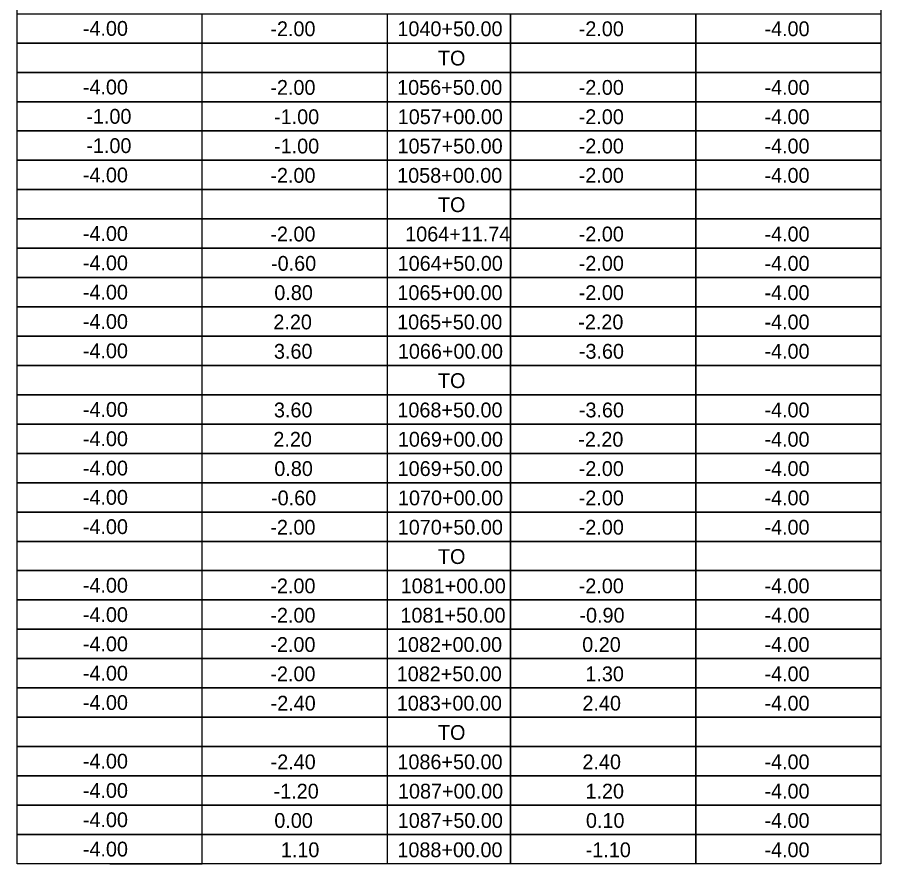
# Model space of a CAD drawing. Extents: x 1026502 to 1027102, y 781811 to 782040.
# Drawn here: x 1027034.42 to 1027062.42, y 781866.07 to 781893.52 of the extents above; entities that cross this region are included whole.
import ezdxf

# ---------------------------------------------------------------- set-up
doc = ezdxf.new("R2010")
doc.units = 0
for name, color, linetype in [('ANNOTATION', 7, 'Continuous'), ('BORDER', 7, 'Continuous'), ('DIMENSIONS', 7, 'Continuous')]:
    doc.layers.add(name, color=color, linetype=linetype)

msp = doc.modelspace()

# ---------------------------------------------------------------- linework, layer by layer
at = {"layer": 'ANNOTATION'}
msp.add_lwpolyline([(1027034.415, 781920.244), (1027062.415, 781920.244), (1027062.415, 781866.071), (1027034.415, 781866.071)], close=True, dxfattribs=at)
at = {"layer": 'BORDER'}
for p, q in [((1027037.415, 781892.682), (1027034.415, 781892.682)), ((1027037.415, 781892.682), (1027034.415, 781892.682)), ((1027037.415, 781892.682), (1027040.415, 781892.682)), ((1027037.415, 781891.732), (1027034.415, 781891.732)), ((1027037.415, 781891.732), (1027034.415, 781891.732)), ((1027037.415, 781891.732), (1027040.415, 781891.732)), ((1027037.415, 781890.781), (1027034.415, 781890.781)), ((1027037.415, 781890.781), (1027034.415, 781890.781)), ((1027037.415, 781890.781), (1027040.415, 781890.781)), ((1027037.415, 781889.831), (1027034.415, 781889.831)), ((1027037.415, 781889.831), (1027034.415, 781889.831)), ((1027037.415, 781889.831), (1027040.415, 781889.831)), ((1027037.415, 781888.881), (1027034.415, 781888.881)), ((1027037.415, 781888.881), (1027034.415, 781888.881)), ((1027037.415, 781888.881), (1027040.415, 781888.881)), ((1027037.415, 781887.93), (1027034.415, 781887.93)), ((1027037.415, 781887.93), (1027034.415, 781887.93)), ((1027037.415, 781887.93), (1027040.415, 781887.93)), ((1027037.415, 781886.98), (1027034.415, 781886.98)), ((1027037.415, 781886.98), (1027034.415, 781886.98)), ((1027037.415, 781886.98), (1027040.415, 781886.98)), ((1027037.415, 781886.029), (1027034.415, 781886.029)), ((1027037.415, 781886.029), (1027034.415, 781886.029)), ((1027037.415, 781886.029), (1027040.415, 781886.029)), ((1027037.415, 781885.079), (1027034.415, 781885.079)), ((1027037.415, 781885.079), (1027034.415, 781885.079)), ((1027037.415, 781885.079), (1027040.415, 781885.079)), ((1027037.415, 781884.129), (1027034.415, 781884.129)), ((1027037.415, 781884.129), (1027034.415, 781884.129)), ((1027037.415, 781884.129), (1027040.415, 781884.129)), ((1027037.415, 781883.178), (1027034.415, 781883.178)), ((1027037.415, 781883.178), (1027034.415, 781883.178)), ((1027037.415, 781883.178), (1027040.415, 781883.178)), ((1027037.415, 781882.228), (1027034.415, 781882.228)), ((1027037.415, 781882.228), (1027034.415, 781882.228)), ((1027037.415, 781882.228), (1027040.415, 781882.228)), ((1027037.415, 781881.277), (1027034.415, 781881.277)), ((1027037.415, 781881.277), (1027034.415, 781881.277)), ((1027037.415, 781881.277), (1027040.415, 781881.277)), ((1027037.415, 781880.327), (1027034.415, 781880.327)), ((1027037.415, 781880.327), (1027034.415, 781880.327)), ((1027037.415, 781880.327), (1027040.415, 781880.327)), ((1027037.415, 781879.377), (1027034.415, 781879.377)), ((1027037.415, 781879.377), (1027034.415, 781879.377)), ((1027037.415, 781879.377), (1027040.415, 781879.377)), ((1027037.415, 781878.426), (1027034.415, 781878.426)), ((1027037.415, 781878.426), (1027034.415, 781878.426)), ((1027037.415, 781878.426), (1027040.415, 781878.426)), ((1027037.415, 781877.476), (1027034.415, 781877.476)), ((1027037.415, 781877.476), (1027034.415, 781877.476)), ((1027037.415, 781877.476), (1027040.415, 781877.476)), ((1027037.415, 781876.525), (1027034.415, 781876.525)), ((1027037.415, 781876.525), (1027034.415, 781876.525)), ((1027037.415, 781876.525), (1027040.415, 781876.525)), ((1027037.415, 781875.575), (1027034.415, 781875.575)), ((1027037.415, 781875.575), (1027034.415, 781875.575)), ((1027037.415, 781875.575), (1027040.415, 781875.575)), ((1027037.415, 781874.625), (1027034.415, 781874.625)), ((1027037.415, 781874.625), (1027034.415, 781874.625)), ((1027037.415, 781874.625), (1027040.415, 781874.625)), ((1027037.415, 781873.674), (1027034.415, 781873.674)), ((1027037.415, 781873.674), (1027034.415, 781873.674)), ((1027037.415, 781873.674), (1027040.415, 781873.674)), ((1027037.415, 781872.724), (1027034.415, 781872.724)), ((1027037.415, 781872.724), (1027034.415, 781872.724)), ((1027037.415, 781872.724), (1027040.415, 781872.724)), ((1027037.415, 781871.773), (1027034.415, 781871.773)), ((1027037.415, 781871.773), (1027034.415, 781871.773)), ((1027037.415, 781871.773), (1027040.415, 781871.773)), ((1027037.415, 781870.823), (1027034.415, 781870.823)), ((1027037.415, 781870.823), (1027034.415, 781870.823)), ((1027037.415, 781870.823), (1027040.415, 781870.823)), ((1027037.415, 781869.873), (1027034.415, 781869.873)), ((1027037.415, 781869.873), (1027034.415, 781869.873)), ((1027037.415, 781869.873), (1027040.415, 781869.873)), ((1027037.415, 781868.922), (1027034.415, 781868.922)), ((1027037.415, 781868.922), (1027034.415, 781868.922)), ((1027037.415, 781868.922), (1027040.415, 781868.922)), ((1027037.415, 781867.972), (1027034.415, 781867.972)), ((1027037.415, 781867.972), (1027034.415, 781867.972)), ((1027037.415, 781867.972), (1027040.415, 781867.972)), ((1027037.415, 781867.021), (1027034.415, 781867.021)), ((1027037.415, 781867.021), (1027034.415, 781867.021)), ((1027037.415, 781867.021), (1027040.415, 781867.021)), ((1027037.415, 781866.071), (1027034.415, 781866.071)), ((1027037.415, 781866.071), (1027034.415, 781866.071)), ((1027037.415, 781866.071), (1027040.415, 781866.071))]:
    msp.add_line(p, q, dxfattribs=at)
for points in [[(1027034.415, 781893.633), (1027062.415, 781893.633), (1027062.415, 781892.682), (1027034.415, 781892.682)], [(1027034.415, 781892.682), (1027062.415, 781892.682), (1027062.415, 781891.732), (1027034.415, 781891.732)], [(1027034.415, 781891.732), (1027062.415, 781891.732), (1027062.415, 781890.781), (1027034.415, 781890.781)], [(1027034.415, 781890.781), (1027062.415, 781890.781), (1027062.415, 781889.831), (1027034.415, 781889.831)], [(1027034.415, 781889.831), (1027062.415, 781889.831), (1027062.415, 781888.881), (1027034.415, 781888.881)], [(1027034.415, 781888.881), (1027062.415, 781888.881), (1027062.415, 781887.93), (1027034.415, 781887.93)], [(1027034.415, 781887.93), (1027062.415, 781887.93), (1027062.415, 781886.98), (1027034.415, 781886.98)], [(1027034.415, 781886.98), (1027062.415, 781886.98), (1027062.415, 781886.029), (1027034.415, 781886.029)], [(1027034.415, 781886.029), (1027062.415, 781886.029), (1027062.415, 781885.079), (1027034.415, 781885.079)], [(1027034.415, 781885.079), (1027062.415, 781885.079), (1027062.415, 781884.129), (1027034.415, 781884.129)], [(1027034.415, 781884.129), (1027062.415, 781884.129), (1027062.415, 781883.178), (1027034.415, 781883.178)], [(1027034.415, 781883.178), (1027062.415, 781883.178), (1027062.415, 781882.228), (1027034.415, 781882.228)], [(1027034.415, 781882.228), (1027062.415, 781882.228), (1027062.415, 781881.277), (1027034.415, 781881.277)], [(1027034.415, 781881.277), (1027062.415, 781881.277), (1027062.415, 781880.327), (1027034.415, 781880.327)], [(1027034.415, 781880.327), (1027062.415, 781880.327), (1027062.415, 781879.377), (1027034.415, 781879.377)], [(1027034.415, 781879.377), (1027062.415, 781879.377), (1027062.415, 781878.426), (1027034.415, 781878.426)], [(1027034.415, 781878.426), (1027062.415, 781878.426), (1027062.415, 781877.476), (1027034.415, 781877.476)], [(1027034.415, 781877.476), (1027062.415, 781877.476), (1027062.415, 781876.525), (1027034.415, 781876.525)], [(1027034.415, 781876.525), (1027062.415, 781876.525), (1027062.415, 781875.575), (1027034.415, 781875.575)], [(1027034.415, 781875.575), (1027062.415, 781875.575), (1027062.415, 781874.625), (1027034.415, 781874.625)], [(1027034.415, 781874.625), (1027062.415, 781874.625), (1027062.415, 781873.674), (1027034.415, 781873.674)], [(1027034.415, 781873.674), (1027062.415, 781873.674), (1027062.415, 781872.724), (1027034.415, 781872.724)], [(1027034.415, 781872.724), (1027062.415, 781872.724), (1027062.415, 781871.773), (1027034.415, 781871.773)], [(1027034.415, 781871.773), (1027062.415, 781871.773), (1027062.415, 781870.823), (1027034.415, 781870.823)], [(1027034.415, 781870.823), (1027062.415, 781870.823), (1027062.415, 781869.873), (1027034.415, 781869.873)], [(1027034.415, 781869.873), (1027062.415, 781869.873), (1027062.415, 781868.922), (1027034.415, 781868.922)], [(1027034.415, 781868.922), (1027062.415, 781868.922), (1027062.415, 781867.972), (1027034.415, 781867.972)], [(1027034.415, 781867.972), (1027062.415, 781867.972), (1027062.415, 781867.021), (1027034.415, 781867.021)], [(1027034.415, 781867.021), (1027062.415, 781867.021), (1027062.415, 781866.071), (1027034.415, 781866.071)]]:
    msp.add_lwpolyline(points, close=True, dxfattribs=at)
for points in [[(1027046.415, 781893.633), (1027046.415, 781892.682), (1027040.415, 781892.682), (1027040.415, 781893.633)], [(1027050.415, 781893.633), (1027050.415, 781892.682), (1027046.415, 781892.682)], [(1027056.415, 781893.633), (1027056.415, 781892.682), (1027050.415, 781892.682), (1027050.415, 781893.633)], [(1027062.415, 781893.633), (1027062.415, 781892.682), (1027056.415, 781892.682), (1027056.415, 781893.633)], [(1027046.415, 781892.682), (1027046.415, 781891.732), (1027040.415, 781891.732), (1027040.415, 781892.682)], [(1027050.415, 781892.682), (1027050.415, 781891.732), (1027046.415, 781891.732)], [(1027056.415, 781892.682), (1027056.415, 781891.732), (1027050.415, 781891.732), (1027050.415, 781892.682)], [(1027062.415, 781892.682), (1027062.415, 781891.732), (1027056.415, 781891.732), (1027056.415, 781892.682)], [(1027046.415, 781891.732), (1027046.415, 781890.781), (1027040.415, 781890.781), (1027040.415, 781891.732)], [(1027050.415, 781891.732), (1027050.415, 781890.781), (1027046.415, 781890.781)], [(1027056.415, 781891.732), (1027056.415, 781890.781), (1027050.415, 781890.781), (1027050.415, 781891.732)], [(1027062.415, 781891.732), (1027062.415, 781890.781), (1027056.415, 781890.781), (1027056.415, 781891.732)], [(1027046.415, 781890.781), (1027046.415, 781889.831), (1027040.415, 781889.831), (1027040.415, 781890.781)], [(1027050.415, 781890.781), (1027050.415, 781889.831), (1027046.415, 781889.831)], [(1027056.415, 781890.781), (1027056.415, 781889.831), (1027050.415, 781889.831), (1027050.415, 781890.781)], [(1027062.415, 781890.781), (1027062.415, 781889.831), (1027056.415, 781889.831), (1027056.415, 781890.781)], [(1027046.415, 781889.831), (1027046.415, 781888.881), (1027040.415, 781888.881), (1027040.415, 781889.831)], [(1027050.415, 781889.831), (1027050.415, 781888.881), (1027046.415, 781888.881)], [(1027056.415, 781889.831), (1027056.415, 781888.881), (1027050.415, 781888.881), (1027050.415, 781889.831)], [(1027062.415, 781889.831), (1027062.415, 781888.881), (1027056.415, 781888.881), (1027056.415, 781889.831)], [(1027046.415, 781888.881), (1027046.415, 781887.93), (1027040.415, 781887.93), (1027040.415, 781888.881)], [(1027050.415, 781888.881), (1027050.415, 781887.93), (1027046.415, 781887.93)], [(1027056.415, 781888.881), (1027056.415, 781887.93), (1027050.415, 781887.93), (1027050.415, 781888.881)], [(1027062.415, 781888.881), (1027062.415, 781887.93), (1027056.415, 781887.93), (1027056.415, 781888.881)], [(1027046.415, 781887.93), (1027046.415, 781886.98), (1027040.415, 781886.98), (1027040.415, 781887.93)], [(1027050.415, 781887.93), (1027050.415, 781886.98), (1027046.415, 781886.98)], [(1027056.415, 781887.93), (1027056.415, 781886.98), (1027050.415, 781886.98), (1027050.415, 781887.93)], [(1027062.415, 781887.93), (1027062.415, 781886.98), (1027056.415, 781886.98), (1027056.415, 781887.93)], [(1027046.415, 781886.98), (1027046.415, 781886.029), (1027040.415, 781886.029), (1027040.415, 781886.98)], [(1027050.415, 781886.98), (1027050.415, 781886.029), (1027046.415, 781886.029)], [(1027056.415, 781886.98), (1027056.415, 781886.029), (1027050.415, 781886.029), (1027050.415, 781886.98)], [(1027062.415, 781886.98), (1027062.415, 781886.029), (1027056.415, 781886.029), (1027056.415, 781886.98)], [(1027046.415, 781886.029), (1027046.415, 781885.079), (1027040.415, 781885.079), (1027040.415, 781886.029)], [(1027050.415, 781886.029), (1027050.415, 781885.079), (1027046.415, 781885.079)], [(1027056.415, 781886.029), (1027056.415, 781885.079), (1027050.415, 781885.079), (1027050.415, 781886.029)], [(1027062.415, 781886.029), (1027062.415, 781885.079), (1027056.415, 781885.079), (1027056.415, 781886.029)], [(1027046.415, 781885.079), (1027046.415, 781884.129), (1027040.415, 781884.129), (1027040.415, 781885.079)], [(1027050.415, 781885.079), (1027050.415, 781884.129), (1027046.415, 781884.129)], [(1027056.415, 781885.079), (1027056.415, 781884.129), (1027050.415, 781884.129), (1027050.415, 781885.079)], [(1027062.415, 781885.079), (1027062.415, 781884.129), (1027056.415, 781884.129), (1027056.415, 781885.079)], [(1027046.415, 781884.129), (1027046.415, 781883.178), (1027040.415, 781883.178), (1027040.415, 781884.129)], [(1027050.415, 781884.129), (1027050.415, 781883.178), (1027046.415, 781883.178)], [(1027056.415, 781884.129), (1027056.415, 781883.178), (1027050.415, 781883.178), (1027050.415, 781884.129)], [(1027062.415, 781884.129), (1027062.415, 781883.178), (1027056.415, 781883.178), (1027056.415, 781884.129)], [(1027046.415, 781883.178), (1027046.415, 781882.228), (1027040.415, 781882.228), (1027040.415, 781883.178)], [(1027050.415, 781883.178), (1027050.415, 781882.228), (1027046.415, 781882.228)], [(1027056.415, 781883.178), (1027056.415, 781882.228), (1027050.415, 781882.228), (1027050.415, 781883.178)], [(1027062.415, 781883.178), (1027062.415, 781882.228), (1027056.415, 781882.228), (1027056.415, 781883.178)], [(1027046.415, 781882.228), (1027046.415, 781881.277), (1027040.415, 781881.277), (1027040.415, 781882.228)], [(1027050.415, 781882.228), (1027050.415, 781881.277), (1027046.415, 781881.277)], [(1027056.415, 781882.228), (1027056.415, 781881.277), (1027050.415, 781881.277), (1027050.415, 781882.228)], [(1027062.415, 781882.228), (1027062.415, 781881.277), (1027056.415, 781881.277), (1027056.415, 781882.228)], [(1027046.415, 781881.277), (1027046.415, 781880.327), (1027040.415, 781880.327), (1027040.415, 781881.277)], [(1027050.415, 781881.277), (1027050.415, 781880.327), (1027046.415, 781880.327)], [(1027056.415, 781881.277), (1027056.415, 781880.327), (1027050.415, 781880.327), (1027050.415, 781881.277)], [(1027062.415, 781881.277), (1027062.415, 781880.327), (1027056.415, 781880.327), (1027056.415, 781881.277)], [(1027046.415, 781880.327), (1027046.415, 781879.377), (1027040.415, 781879.377), (1027040.415, 781880.327)], [(1027050.415, 781880.327), (1027050.415, 781879.377), (1027046.415, 781879.377)], [(1027056.415, 781880.327), (1027056.415, 781879.377), (1027050.415, 781879.377), (1027050.415, 781880.327)], [(1027062.415, 781880.327), (1027062.415, 781879.377), (1027056.415, 781879.377), (1027056.415, 781880.327)], [(1027046.415, 781879.377), (1027046.415, 781878.426), (1027040.415, 781878.426), (1027040.415, 781879.377)], [(1027050.415, 781879.377), (1027050.415, 781878.426), (1027046.415, 781878.426)], [(1027056.415, 781879.377), (1027056.415, 781878.426), (1027050.415, 781878.426), (1027050.415, 781879.377)], [(1027062.415, 781879.377), (1027062.415, 781878.426), (1027056.415, 781878.426), (1027056.415, 781879.377)], [(1027046.415, 781878.426), (1027046.415, 781877.476), (1027040.415, 781877.476), (1027040.415, 781878.426)], [(1027050.415, 781878.426), (1027050.415, 781877.476), (1027046.415, 781877.476)], [(1027056.415, 781878.426), (1027056.415, 781877.476), (1027050.415, 781877.476), (1027050.415, 781878.426)], [(1027062.415, 781878.426), (1027062.415, 781877.476), (1027056.415, 781877.476), (1027056.415, 781878.426)], [(1027046.415, 781877.476), (1027046.415, 781876.525), (1027040.415, 781876.525), (1027040.415, 781877.476)], [(1027050.415, 781877.476), (1027050.415, 781876.525), (1027046.415, 781876.525)], [(1027056.415, 781877.476), (1027056.415, 781876.525), (1027050.415, 781876.525), (1027050.415, 781877.476)], [(1027062.415, 781877.476), (1027062.415, 781876.525), (1027056.415, 781876.525), (1027056.415, 781877.476)], [(1027046.415, 781876.525), (1027046.415, 781875.575), (1027040.415, 781875.575), (1027040.415, 781876.525)], [(1027050.415, 781876.525), (1027050.415, 781875.575), (1027046.415, 781875.575)], [(1027056.415, 781876.525), (1027056.415, 781875.575), (1027050.415, 781875.575), (1027050.415, 781876.525)], [(1027062.415, 781876.525), (1027062.415, 781875.575), (1027056.415, 781875.575), (1027056.415, 781876.525)], [(1027046.415, 781875.575), (1027046.415, 781874.625), (1027040.415, 781874.625), (1027040.415, 781875.575)], [(1027050.415, 781875.575), (1027050.415, 781874.625), (1027046.415, 781874.625)], [(1027056.415, 781875.575), (1027056.415, 781874.625), (1027050.415, 781874.625), (1027050.415, 781875.575)], [(1027062.415, 781875.575), (1027062.415, 781874.625), (1027056.415, 781874.625), (1027056.415, 781875.575)], [(1027046.415, 781874.625), (1027046.415, 781873.674), (1027040.415, 781873.674), (1027040.415, 781874.625)], [(1027050.415, 781874.625), (1027050.415, 781873.674), (1027046.415, 781873.674)], [(1027056.415, 781874.625), (1027056.415, 781873.674), (1027050.415, 781873.674), (1027050.415, 781874.625)], [(1027062.415, 781874.625), (1027062.415, 781873.674), (1027056.415, 781873.674), (1027056.415, 781874.625)], [(1027046.415, 781873.674), (1027046.415, 781872.724), (1027040.415, 781872.724), (1027040.415, 781873.674)], [(1027050.415, 781873.674), (1027050.415, 781872.724), (1027046.415, 781872.724)], [(1027056.415, 781873.674), (1027056.415, 781872.724), (1027050.415, 781872.724), (1027050.415, 781873.674)], [(1027062.415, 781873.674), (1027062.415, 781872.724), (1027056.415, 781872.724), (1027056.415, 781873.674)], [(1027046.415, 781872.724), (1027046.415, 781871.773), (1027040.415, 781871.773), (1027040.415, 781872.724)], [(1027050.415, 781872.724), (1027050.415, 781871.773), (1027046.415, 781871.773)], [(1027056.415, 781872.724), (1027056.415, 781871.773), (1027050.415, 781871.773), (1027050.415, 781872.724)], [(1027062.415, 781872.724), (1027062.415, 781871.773), (1027056.415, 781871.773), (1027056.415, 781872.724)], [(1027046.415, 781871.773), (1027046.415, 781870.823), (1027040.415, 781870.823), (1027040.415, 781871.773)], [(1027050.415, 781871.773), (1027050.415, 781870.823), (1027046.415, 781870.823)], [(1027056.415, 781871.773), (1027056.415, 781870.823), (1027050.415, 781870.823), (1027050.415, 781871.773)], [(1027062.415, 781871.773), (1027062.415, 781870.823), (1027056.415, 781870.823), (1027056.415, 781871.773)], [(1027046.415, 781870.823), (1027046.415, 781869.873), (1027040.415, 781869.873), (1027040.415, 781870.823)], [(1027050.415, 781870.823), (1027050.415, 781869.873), (1027046.415, 781869.873)], [(1027056.415, 781870.823), (1027056.415, 781869.873), (1027050.415, 781869.873), (1027050.415, 781870.823)], [(1027062.415, 781870.823), (1027062.415, 781869.873), (1027056.415, 781869.873), (1027056.415, 781870.823)], [(1027046.415, 781869.873), (1027046.415, 781868.922), (1027040.415, 781868.922), (1027040.415, 781869.873)], [(1027050.415, 781869.873), (1027050.415, 781868.922), (1027046.415, 781868.922)], [(1027056.415, 781869.873), (1027056.415, 781868.922), (1027050.415, 781868.922), (1027050.415, 781869.873)], [(1027062.415, 781869.873), (1027062.415, 781868.922), (1027056.415, 781868.922), (1027056.415, 781869.873)], [(1027046.415, 781868.922), (1027046.415, 781867.972), (1027040.415, 781867.972), (1027040.415, 781868.922)], [(1027050.415, 781868.922), (1027050.415, 781867.972), (1027046.415, 781867.972)], [(1027056.415, 781868.922), (1027056.415, 781867.972), (1027050.415, 781867.972), (1027050.415, 781868.922)], [(1027062.415, 781868.922), (1027062.415, 781867.972), (1027056.415, 781867.972), (1027056.415, 781868.922)], [(1027046.415, 781867.972), (1027046.415, 781867.021), (1027040.415, 781867.021), (1027040.415, 781867.972)], [(1027050.415, 781867.972), (1027050.415, 781867.021), (1027046.415, 781867.021)], [(1027056.415, 781867.972), (1027056.415, 781867.021), (1027050.415, 781867.021), (1027050.415, 781867.972)], [(1027062.415, 781867.972), (1027062.415, 781867.021), (1027056.415, 781867.021), (1027056.415, 781867.972)], [(1027046.415, 781867.021), (1027046.415, 781866.071), (1027040.415, 781866.071), (1027040.415, 781867.021)], [(1027050.415, 781867.021), (1027050.415, 781866.071), (1027046.415, 781866.071)], [(1027056.415, 781867.021), (1027056.415, 781866.071), (1027050.415, 781866.071), (1027050.415, 781867.021)], [(1027062.415, 781867.021), (1027062.415, 781866.071), (1027056.415, 781866.071), (1027056.415, 781867.021)]]:
    msp.add_lwpolyline(points, dxfattribs=at)

# ---------------------------------------------------------------- texts
at = {"layer": 'DIMENSIONS'}
for s, p in [('-4.00', (1027036.542, 781892.917)), ('-2.00', (1027042.622, 781892.906)), ('1040+50.00', (1027046.742, 781892.906)), ('-2.00', (1027052.622, 781892.906)), ('-4.00', (1027058.645, 781892.906)), ('TO', (1027048.057, 781891.955)), ('-4.00', (1027036.542, 781891.017)), ('-2.00', (1027042.622, 781891.004)), ('1056+50.00', (1027046.734, 781891.004)), ('-2.00', (1027052.622, 781891.004)), ('-4.00', (1027058.645, 781891.004)), ('-1.00', (1027036.654, 781890.066)), ('-1.00', (1027042.743, 781890.054)), ('1057+00.00', (1027046.753, 781890.054)), ('-2.00', (1027052.622, 781890.054)), ('-4.00', (1027058.645, 781890.054)), ('-1.00', (1027036.654, 781889.116)), ('-1.00', (1027042.743, 781889.103)), ('1057+50.00', (1027046.746, 781889.103)), ('-2.00', (1027052.622, 781889.103)), ('-4.00', (1027058.645, 781889.103)), ('-4.00', (1027036.542, 781888.165)), ('-2.00', (1027042.622, 781888.152)), ('1058+00.00', (1027046.734, 781888.152)), ('-2.00', (1027052.622, 781888.152)), ('-4.00', (1027058.645, 781888.152)), ('TO', (1027048.057, 781887.201)), ('-4.00', (1027036.542, 781886.265)), ('-2.00', (1027042.622, 781886.25)), ('1064+11.74', (1027046.995, 781886.25)), ('-2.00', (1027052.622, 781886.25)), ('-4.00', (1027058.645, 781886.25)), ('-4.00', (1027036.542, 781885.314)), ('-0.60', (1027042.645, 781885.299)), ('1064+50.00', (1027046.75, 781885.299)), ('-2.00', (1027052.622, 781885.299)), ('-4.00', (1027058.645, 781885.299)), ('-4.00', (1027036.542, 781884.364)), ('0.80', (1027042.751, 781884.349)), ('1065+00.00', (1027046.742, 781884.349)), ('-2.00', (1027052.622, 781884.349)), ('-4.00', (1027058.645, 781884.349)), ('-4.00', (1027036.542, 781883.413)), ('2.20', (1027042.72, 781883.398)), ('1065+50.00', (1027046.734, 781883.398)), ('-2.20', (1027052.607, 781883.398)), ('-4.00', (1027058.645, 781883.398)), ('-4.00', (1027036.542, 781882.463)), ('3.60', (1027042.739, 781882.447)), ('1066+00.00', (1027046.757, 781882.447)), ('-3.60', (1027052.626, 781882.447)), ('-4.00', (1027058.645, 781882.447)), ('TO', (1027048.057, 781881.496)), ('-4.00', (1027036.542, 781880.562)), ('3.60', (1027042.739, 781880.545)), ('1068+50.00', (1027046.742, 781880.545)), ('-3.60', (1027052.626, 781880.545)), ('-4.00', (1027058.645, 781880.545)), ('-4.00', (1027036.542, 781879.612)), ('2.20', (1027042.72, 781879.594)), ('1069+00.00', (1027046.757, 781879.594)), ('-2.20', (1027052.607, 781879.594)), ('-4.00', (1027058.645, 781879.594)), ('-4.00', (1027036.542, 781878.661)), ('0.80', (1027042.751, 781878.644)), ('1069+50.00', (1027046.75, 781878.644)), ('-2.00', (1027052.622, 781878.644)), ('-4.00', (1027058.645, 781878.644)), ('-4.00', (1027036.542, 781877.711)), ('-0.60', (1027042.645, 781877.693)), ('1070+00.00', (1027046.761, 781877.693)), ('-2.00', (1027052.622, 781877.693)), ('-4.00', (1027058.645, 781877.693)), ('-4.00', (1027036.542, 781876.761)), ('-2.00', (1027042.622, 781876.742)), ('1070+50.00', (1027046.753, 781876.742)), ('-2.00', (1027052.622, 781876.742)), ('-4.00', (1027058.645, 781876.742)), ('TO', (1027048.057, 781875.791)), ('-4.00', (1027036.542, 781874.86)), ('-2.00', (1027042.622, 781874.84)), ('1081+00.00', (1027046.848, 781874.84)), ('-2.00', (1027052.622, 781874.84)), ('-4.00', (1027058.645, 781874.84)), ('-4.00', (1027036.542, 781873.909)), ('-2.00', (1027042.622, 781873.889)), ('1081+50.00', (1027046.84, 781873.889)), ('-0.90', (1027052.645, 781873.889)), ('-4.00', (1027058.645, 781873.889)), ('-4.00', (1027036.542, 781872.959)), ('-2.00', (1027042.622, 781872.939)), ('1082+00.00', (1027046.727, 781872.939)), ('0.20', (1027052.736, 781872.939)), ('-4.00', (1027058.645, 781872.939)), ('-4.00', (1027036.542, 781872.009)), ('-2.00', (1027042.622, 781871.988)), ('1082+50.00', (1027046.719, 781871.988)), ('1.30', (1027052.838, 781871.988)), ('-4.00', (1027058.645, 781871.988)), ('-4.00', (1027036.542, 781871.058)), ('-2.40', (1027042.63, 781871.037)), ('1083+00.00', (1027046.723, 781871.037)), ('2.40', (1027052.743, 781871.037)), ('-4.00', (1027058.645, 781871.037)), ('TO', (1027048.057, 781870.086)), ('-4.00', (1027036.542, 781869.157)), ('-2.40', (1027042.63, 781869.135)), ('1086+50.00', (1027046.742, 781869.135)), ('2.40', (1027052.743, 781869.135)), ('-4.00', (1027058.645, 781869.135)), ('-4.00', (1027036.542, 781868.207)), ('-1.20', (1027042.728, 781868.184)), ('1087+00.00', (1027046.761, 781868.184)), ('1.20', (1027052.841, 781868.184)), ('-4.00', (1027058.645, 781868.184)), ('-4.00', (1027036.542, 781867.257)), ('0.00', (1027042.751, 781867.234)), ('1087+50.00', (1027046.753, 781867.234)), ('0.10', (1027052.856, 781867.234)), ('-4.00', (1027058.645, 781867.234)), ('-4.00', (1027036.542, 781866.306)), ('1.10', (1027042.962, 781866.283)), ('1088+00.00', (1027046.742, 781866.283)), ('-1.10', (1027052.849, 781866.283)), ('-4.00', (1027058.645, 781866.283))]:
    msp.add_text(s, height=0.48, dxfattribs=at).set_placement(p)

doc.saveas('drawing.dxf')
